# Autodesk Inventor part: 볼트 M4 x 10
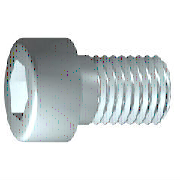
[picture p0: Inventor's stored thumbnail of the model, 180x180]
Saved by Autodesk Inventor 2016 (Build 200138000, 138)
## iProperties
IsCustomPart: 0
Created: 2016-04
Part Number: 볼트 M4 x 10
Material: 강철, 연강
Description: 6각머리 태핑 나사
Document SubType Name: Modeling
Standard: KS B 1003
Designer: mdu
Standards Organization: KS
Language: ko-KR
Size Designation: M 4 x 10
Categories: <MemberInstance><Categories><Category DisplayName="조임쇠" InternalName="e4da775c-781d-43d5-af7c-5136215cf5a6" Mnemonic="FSTN"><Category DisplayName="볼트" InternalN
Density: 7.86 g/cm^3
Mass: 2.0371 g
Surface Area: 3.0572 cm^2
Volume: 0.259174 cm^3
Appearance: 금속 1800F 열
Author: mdu
Revision Number: 1
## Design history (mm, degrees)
sketch "스케치1"
  geometry: L1 (-1, 0)-(10, 0); L2 (10, 0)-(10, 2); L3 (10, 2)-(1.75, 2); L4 (1.75, 2)-(1.32, 2); L5 (1.32, 2)-(0, 2); L6 (0, 2)-(0, 3.5); L7 (0, 3.5)-(-4, 3.5); L8 (-4, 3.5)-(-4, 1.732); L9 (-4, 1.732)-(-2, 1.732); L10 (-2, 1.732)-(-1, 0); L11 (-6.8, 0)-(12.8, 0) reference; L12 (0, -0.7)-(0, 4.2) reference; L13 (1.75, 2)-(0, 2)
  constraints: 22 end point, 6 parallel, 2 collinear, 2 perpendicular, 1 horizontal, 1 point on line
  dimensions: "d1" = 8.25 distance from line of L3.end L2 (= GEL); "d2" = 0.42952 distance of L4.end L3.end (computed from GAL); "d3" = 4 distance between parallel lines of L8 L6 (= KOH); "d4" = 2 distance of L8.end L9.end (= INTI); "d5" = 60 deg angle of L10 L1; "d6" = 4 diameter of L3 L1 (= GD); "d7" = 4 diameter of L5 L1 (= BDM); "d8" = 3.4641 diameter of L9 L1 (= 1.1547 x SW); "d9" = 7 diameter of L7 L1 (= KOD); "d26" = 10 distance between parallel lines of L12 L2 (= NLG)
revolve "본체" sketch "스케치1" stored, may be unused: angle "d10" = 90 deg
sketch "스케치2"
  geometry: L1 (0, -4.9)-(0, 4.9) reference; L2 (-4.9, 0)-(4.9, 0) reference; L3 (1.732, 0)-(0.866, -1.5); L4 (0.866, -1.5)-(-0.866, -1.5); L5 (-0.866, -1.5)-(-1.732, 0); L6 (-1.732, 0)-(-0.866, 1.5); L7 (-0.866, 1.5)-(0.866, 1.5); L8 (0.866, 1.5)-(1.732, 0); 2 further points
  constraints: 12 end point, 1 coincident, 1 horizontal alignment, 1 point on line, 12 other
extrude "슬롯" join sketch "스케치2" stored distance "d11" = 10; taper "d12" = 0 deg
workplane "Work Plane1"
fillet "Fillet2" dims "d30" = 0.1 (= R)
body "Solid1"
fillet "모깎기1" dims "d17" = 0.4 (= RR)
feature "스레드" dims "d13" = 8.25 (= GEL), "d14" = 0
chamfer "모따기1" distance "d15" = 0.42941 (= -0.5 x SPD + 0.5 x GD); stored, may be unused: second distance "d16" = 0.42941 (= GUL), angle "d27" = 45 deg
other parameters: "GD" = 4 (= NND) [user parameter; used in 2 equation terms], "NLG" = 10 [user parameter; used in 1 equation term], "GEL" = 8.25 [user parameter; used in 2 equation terms], "KOD" = 7 [user parameter; used in 1 equation term], "KOH" = 4 [user parameter; used in 1 equation term], "INTI" = 2 [user parameter; used in 1 equation term], "GAL" = 0.42941 (= 0.61345 x PTC) [user parameter; used in 1 equation term], "GUL" = 0.42941 (= 0.61345 x PTC) [user parameter; used in 1 equation term], "BDM" = 4 (= NND) [user parameter; used in 1 equation term], "SW" = 3 [user parameter; used in 2 equation terms], "RR" = 0.4 [user parameter; used in 1 equation term], "SPD" = 3.14117 (= NND - 1.2269 x PTC) [user parameter; used in 1 equation term], "d19" = 0, "d28" = 0, "d29" = 0, "R" = 0.1 [user parameter; used in 1 equation term], "PHH" = 0.2 [user parameter], "GD1" = 3.14117 (= THREADDIA - 1.2269 x PTC) [user parameter], "THREADDIA" = 4 [user parameter; used in 1 equation term], "FAWI" = 45 deg [user parameter], "TPU" = 14.28571 (computed from PTC) [user parameter], "PTC" = 0.7 [user parameter; used in 5 equation terms], "NND" = 4 [user parameter; used in 3 equation terms], "TOA" = 30 deg [user parameter], "E0" = 3.465 (= 1.155 x SW) [user parameter]
